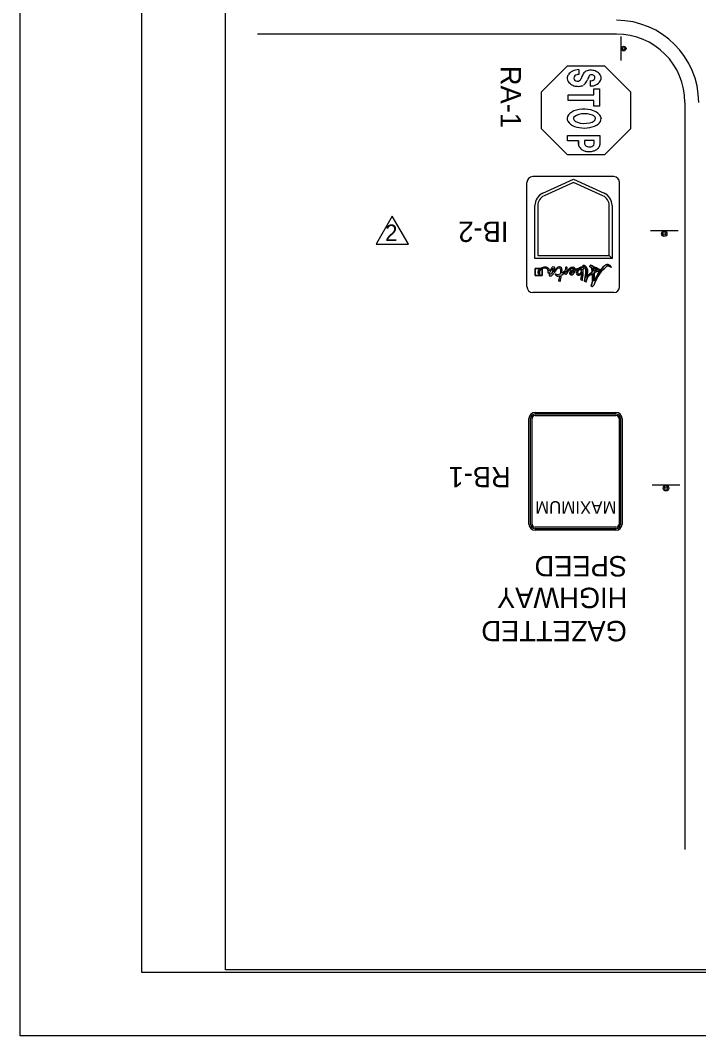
# Model space of a CAD drawing. Extents: x 1482 to 1692, y 225 to 494.
# Drawn here: x 1482.4 to 1542.3, y 224.6 to 314.2 of the extents above; entities that cross this region are included whole.
import ezdxf

# ---------------------------------------------------------------- set-up
doc = ezdxf.new("R2010")
doc.units = 0
for name, color, linetype in [('Level 17', 7, 'Continuous'), ('Level 2', 7, 'Continuous'), ('Level 53', 7, 'Continuous'), ('Level 60', 7, 'Continuous')]:
    doc.layers.add(name, color=color, linetype=linetype)

msp = doc.modelspace()

# ---------------------------------------------------------------- linework, layer by layer
at = {"layer": 'Level 17'}
for p, q in [((1535.424, 312.793), (1535.424, 310.66)), ((1531.14, 309.729), (1531.142, 309.732)), ((1531.708, 309.872), (1531.708, 309.422)), ((1532.74, 308.415), (1532.74, 308.907)), ((1533.04, 307.653), (1533.04, 308.181)), ((1533.04, 308.181), (1533.543, 308.181)), ((1533.543, 308.181), (1533.543, 306.651)), ((1530.78, 307.155), (1530.78, 307.653)), ((1530.78, 307.653), (1533.04, 307.653)), ((1533.028, 307.155), (1530.78, 307.155)), ((1533.028, 306.651), (1533.028, 307.155)), ((1533.543, 306.651), (1533.028, 306.651)), ((1533.182, 305.594), (1533.186, 305.574)), ((1533.67, 305.574), (1533.672, 305.559)), ((1530.696, 303.57), (1530.696, 304.047)), ((1530.696, 304.047), (1533.57, 304.047)), ((1533.57, 304.047), (1533.57, 303.243)), ((1531.676, 303.57), (1530.696, 303.57)), ((1531.676, 303.57), (1531.676, 303.27)), ((1531.683, 303.284), (1531.676, 303.57)), ((1533.054, 303.627), (1532.218, 303.627)), ((1532.218, 303.627), (1532.218, 303.321)), ((1533.054, 303.627), (1532.218, 303.627)), ((1532.218, 303.627), (1532.218, 303.321)), ((1533.054, 303.315), (1533.054, 303.627)), ((1533.054, 303.315), (1533.054, 303.627)), ((1540.463, 295.653), (1538.044, 295.653)), ((1526.756, 289.984), (1526.756, 289.984)), ((1526.756, 289.984), (1526.756, 289.984)), ((1526.756, 289.984), (1526.756, 289.984)), ((1526.756, 289.984), (1526.756, 289.984)), ((1527.854, 279.623), (1534.983, 279.623)), ((1527.304, 269.777), (1527.304, 279.072)), ((1527.441, 269.777), (1527.441, 279.072)), ((1527.578, 269.777), (1527.578, 279.072)), ((1527.854, 279.485), (1534.983, 279.485)), ((1527.854, 279.349), (1534.983, 279.349)), ((1535.26, 279.072), (1535.26, 269.777)), ((1535.396, 279.072), (1535.396, 269.777)), ((1535.534, 279.072), (1535.534, 269.777)), ((1540.616, 273.203), (1538.197, 273.203)), ((1534.983, 269.501), (1527.854, 269.501)), ((1534.983, 269.365), (1527.854, 269.365)), ((1534.983, 269.228), (1527.854, 269.228)), ((1534.983, 269.225), (1534.983, 269.228)), ((1535.11, 269.282), (1535.11, 269.282)), ((1535.235, 269.334), (1535.235, 269.337))]:
    msp.add_line(p, q, dxfattribs=at)
msp.add_lwpolyline([(1530.716, 302.358), (1528.422, 304.652), (1528.422, 307.918), (1530.716, 310.212), (1533.982, 310.212), (1536.274, 307.918), (1536.274, 304.652), (1533.982, 302.358)], close=True, dxfattribs=at)
for centre, radius in [((1535.662, 311.722), 0.213), ((1535.662, 311.722), 0.107), ((1539.249, 295.382), 0.242), ((1539.249, 295.382), 0.121), ((1539.402, 272.932), 0.242), ((1539.402, 272.932), 0.121)]:
    msp.add_circle(centre, radius, dxfattribs=at)
for centre, radius, start, end in [((1531.173, 309.121), 0.489, 142.05359, 202.73967), ((1531.649, 308.788), 1.07, 118.41538, 143.65531), ((1531.775, 308.37), 1.502, 92.38409, 114.95188), ((1531.603, 309.11), 0.335, 140.6966, 181.45727), ((1531.577, 309.135), 0.31, 185.4374, 224.06255), ((1531.572, 309.064), 0.344, 96.87276, 132.74491), ((1531.701, 308.742), 0.685, 89.01715, 103.51721), ((1531.575, 309.184), 0.348, 304.20826, 344.15525), ((1537.06, 307.1), 5.521, 154.46241, 158.83121), ((1532.708, 309.052), 0.762, 110.4481, 145.11069), ((1532.74, 308.738), 1.071, 84.81715, 105.91834), ((1534.051, 308.414), 1.68, 147.98164, 160.97904), ((1532.833, 309.177), 0.242, 74.13099, 148.14758), ((1532.773, 308.587), 1.219, 67.73321, 87.13918), ((1532.871, 309.146), 0.264, 23.8064, 82.24074), ((1532.849, 309.167), 0.277, 317.30173, 19.01194), ((1532.879, 308.921), 0.87, 33.3662, 65.67344), ((1533.152, 309.121), 0.532, 316.13686, 31.39871), ((1531.438, 309.236), 0.782, 203.14132, 234.99056), ((1531.761, 309.717), 1.361, 235.50918, 253.2894), ((1531.574, 309.27), 0.413, 236.25303, 268.73226), ((1531.64, 310.123), 1.731, 261.24702, 273.9864), ((1531.612, 309.174), 0.319, 262.57609, 300.47756), ((1531.637, 309.613), 1.223, 275.90969, 291.9865), ((1533.523, 306.999), 2.053, 129.47897, 133.42605), ((1531.374, 309.4), 1.175, 316.24648, 337.92633), ((1532.801, 309.296), 0.405, 260.44122, 309.32441), ((1532.719, 309.661), 1.243, 270.69518, 287.14515), ((1532.86, 309.343), 0.898, 284.56402, 319.00631), ((1531.846, 303.254), 0.166, 169.79086, 203.54187), ((1532.368, 303.396), 0.706, 196.60197, 209.80906), ((1532.185, 303.253), 0.478, 205.38384, 232.61875), ((1532.407, 303.454), 0.774, 228.29225, 248.60313), ((1532.407, 303.454), 0.774, 228.29225, 248.60313), ((1532.536, 303.387), 0.325, 191.91914, 235.7868), ((1532.536, 303.387), 0.325, 191.91914, 235.7868), ((1532.584, 303.467), 0.418, 236.50855, 267.0313), ((1532.584, 303.467), 0.418, 236.50855, 267.0313), ((1532.641, 303.511), 0.468, 260.34165, 285.23421), ((1532.641, 303.511), 0.468, 260.34165, 285.23421), ((1532.698, 303.495), 0.44, 278.60306, 304.21696), ((1532.698, 303.495), 0.44, 278.60306, 304.21696), ((1532.782, 303.363), 0.283, 305.11978, 349.31166), ((1532.782, 303.363), 0.283, 305.11978, 349.31166), ((1532.888, 303.435), 0.732, 299.22414, 318.53082), ((1532.888, 303.435), 0.732, 299.22414, 318.53082), ((1533.097, 303.285), 0.477, 314.85284, 355.0441), ((1532.711, 304.209), 1.588, 248.31533, 258.66985), ((1532.616, 303.847), 1.215, 259.75207, 272.79164), ((1532.616, 303.847), 1.215, 259.75207, 272.79164), ((1532.587, 304.143), 1.512, 273.39027, 285.65974), ((1532.816, 303.445), 0.778, 283.06738, 303.76202), ((1527.854, 279.072), 0.55, 90, 180), ((1534.983, 279.072), 0.55, 0, 90), ((1527.854, 279.072), 0.413, 90, 180), ((1527.854, 279.072), 0.276, 90, 180), ((1534.983, 279.072), 0.413, 0, 90), ((1534.983, 279.072), 0.276, 0, 90), ((1527.854, 269.776), 0.55, 180, 270), ((1527.854, 269.776), 0.413, 180, 270), ((1527.854, 269.776), 0.276, 180, 270), ((1534.983, 269.776), 0.55, 270, 0), ((1534.983, 269.776), 0.413, 270, 0), ((1534.983, 269.776), 0.276, 270, 0)]:
    msp.add_arc(centre, radius, start, end, dxfattribs=at)
for centre, major_axis, ratio, start_param, end_param in [((1532.175, 305.547), (-1.497, 0.01), 0.558644, 4.129576, 6.939747), ((1532.175, 305.547), (-1.497, 0.01), 0.558644, 0.656861, 3.168126), ((1532.209, 305.547), (-0.977, -0.005), 0.432619, 3.890436, 7.165085), ((1532.209, 305.547), (-0.977, -0.005), 0.432619, 0.881967, 3.190734), ((1532.209, 305.547), (-0.977, -0.005), 0.432619, 3.239639, 3.888884), ((1532.175, 305.547), (-1.497, 0.01), 0.558644, 3.185857, 4.129398)]:
    msp.add_ellipse(centre, major_axis=major_axis, ratio=ratio, start_param=start_param, end_param=end_param, dxfattribs=at)
at = {"layer": 'Level 2'}
for p, q in [((1535.032, 313.009), (1503.354, 313.009)), ((1541.08, 306.96), (1541.08, 241.05)), ((1534.789, 300.427), (1527.647, 300.427)), ((1528.53, 298.962), (1531.239, 300.194)), ((1531.239, 300.194), (1533.948, 298.962)), ((1527.129, 290.722), (1527.129, 299.909)), ((1531.239, 299.913), (1528.636, 298.729)), ((1533.842, 298.729), (1531.239, 299.913)), ((1535.307, 290.722), (1535.307, 299.909)), ((1527.831, 293.208), (1527.831, 297.876)), ((1528.087, 297.876), (1528.087, 293.464)), ((1534.391, 293.464), (1534.391, 297.876)), ((1534.646, 297.876), (1534.646, 293.208)), ((1534.646, 293.208), (1527.831, 293.208)), ((1528.087, 293.464), (1534.391, 293.464)), ((1534.646, 293.208), (1534.391, 293.464)), ((1534.391, 293.464), (1534.646, 293.208)), ((1534.789, 290.204), (1527.647, 290.204)), ((1534.789, 290.204), (1527.647, 290.204))]:
    msp.add_line(p, q, dxfattribs=at)
for centre, radius, start, end in [((1535.032, 306.96), 7.258, 0, 90), ((1535.032, 306.96), 6.048, 0, 90), ((1527.647, 299.909), 0.518, 90, 180), ((1534.789, 299.909), 0.518, 360, 90), ((1529.024, 297.876), 1.193, 114.45682, 180), ((1529.024, 297.876), 0.937, 114.45682, 180), ((1533.454, 297.876), 0.937, 360, 65.54318), ((1533.454, 297.876), 1.193, 360, 65.54318), ((1527.647, 290.722), 0.518, 180, 270), ((1534.789, 290.722), 0.518, 270, 360)]:
    msp.add_arc(centre, radius, start, end, dxfattribs=at)
at = {"layer": 'Level 53'}
msp.add_line((1528.309, 292.319), (1528.459, 292.319), dxfattribs=at)
msp.add_lwpolyline([(1528.309, 292.319), (1527.868, 292.319), (1527.868, 291.711), (1528.476, 291.711), (1528.476, 292.319), (1528.459, 292.319)], dxfattribs=at)
for points, degree in [([(1528.476, 291.711), (1528.476, 291.711), (1528.476, 292.319), (1528.476, 292.319), (1528.476, 292.319), (1528.459, 292.319), (1528.459, 292.319), (1528.327, 292.241), (1528.238, 292.089), (1528.238, 291.965), (1528.239, 291.858), (1528.295, 291.863), (1528.289, 291.848), (1528.271, 291.805), (1528.136, 291.83), (1528.128, 291.981), (1528.122, 292.11), (1528.189, 292.234), (1528.309, 292.319), (1528.309, 292.319), (1527.868, 292.319), (1527.868, 292.319), (1527.868, 292.319), (1527.868, 291.711), (1527.868, 291.711), (1527.868, 291.711), (1528.476, 291.711), (1528.476, 291.711)], 3), ([(1528.459, 292.319), (1528.327, 292.241), (1528.238, 292.089), (1528.238, 291.965), (1528.239, 291.858), (1528.295, 291.863), (1528.289, 291.848), (1528.271, 291.805), (1528.136, 291.83), (1528.128, 291.981), (1528.122, 292.11), (1528.189, 292.234), (1528.309, 292.319)], 3), ([(1529.12, 292.088), (1529.105, 292.214), (1529.022, 292.43), (1528.685, 292.43), (1528.533, 292.43), (1528.404, 292.387), (1528.309, 292.319)], 3), ([(1528.459, 292.319), (1528.515, 292.353), (1528.579, 292.373), (1528.647, 292.373)], 2), ([(1528.647, 292.373), (1528.896, 292.373), (1528.961, 292.18), (1528.973, 292.083), (1528.981, 292.02), (1528.967, 291.927), (1529.077, 291.94), (1529.155, 291.948), (1529.224, 292.098), (1529.322, 292.225), (1529.406, 292.334), (1529.444, 292.323), (1529.424, 292.23), (1529.4, 292.113), (1529.302, 291.839), (1529.191, 291.819), (1529.139, 291.81), (1529.121, 291.901), (1529.097, 291.844), (1529.073, 291.787), (1529.095, 291.665), (1529.211, 291.665), (1529.291, 291.665), (1529.388, 291.75), (1529.468, 291.848), (1529.537, 291.933), (1529.888, 292.448), (1530.035, 292.337), (1530.103, 292.285), (1530.098, 292.073), (1530.054, 291.823)], 3), ([(1529.488, 292.015), (1529.566, 292.191), (1529.61, 292.417), (1529.493, 292.451), (1529.356, 292.491), (1529.247, 292.263), (1529.12, 292.088)], 3), ([(1530.206, 291.901), (1530.234, 292.137), (1530.224, 292.348), (1530.117, 292.414), (1529.92, 292.538), (1529.642, 292.213), (1529.488, 292.015)], 3), ([(1530.182, 291.737), (1530.311, 291.811), (1530.432, 291.936), (1530.52, 292.099)], 2), ([(1530.632, 291.979), (1530.646, 292.125), (1530.741, 292.445), (1530.579, 292.429), (1530.515, 292.422), (1530.543, 292.412), (1530.539, 292.357), (1530.525, 292.164), (1530.365, 292.001), (1530.206, 291.901)], 3), ([(1530.52, 292.099), (1530.505, 292.024), (1530.481, 291.94), (1530.479, 291.884), (1530.478, 291.825), (1530.518, 291.812), (1530.534, 291.807), (1530.568, 291.797), (1530.61, 291.814), (1530.651, 291.872), (1530.747, 292.008), (1530.869, 292.223), (1531.055, 292.313), (1531.187, 292.377), (1531.246, 292.312), (1531.249, 292.212)], 3), ([(1531.391, 292.246), (1531.377, 292.353), (1531.308, 292.435), (1531.145, 292.42), (1530.915, 292.399), (1530.71, 292.116), (1530.632, 291.979)], 3), ([(1531.249, 292.212), (1531.223, 292.204), (1531.199, 292.196), (1531.179, 292.187), (1530.939, 292.08), (1530.856, 291.919), (1530.917, 291.822), (1530.975, 291.728), (1531.141, 291.757), (1531.272, 291.895), (1531.337, 291.963), (1531.387, 292.08), (1531.392, 292.186)], 3), ([(1531.12, 291.907), (1531.04, 291.832), (1531, 291.837), (1530.989, 291.858), (1530.966, 291.901), (1531.061, 292.055), (1531.243, 292.139)], 3), ([(1531.243, 292.139), (1531.227, 292.056), (1531.184, 291.966), (1531.12, 291.907)], 2), ([(1531.632, 292.285), (1531.552, 292.275), (1531.468, 292.262), (1531.391, 292.246)], 2), ([(1531.392, 292.186), (1531.448, 292.198), (1531.512, 292.209), (1531.583, 292.218)], 2), ([(1531.583, 292.218), (1531.47, 292.035), (1531.48, 291.787), (1531.645, 291.745), (1531.837, 291.697), (1531.934, 291.883), (1531.975, 292.038)], 3), ([(1531.934, 292.254), (1531.908, 292.058), (1531.807, 291.787), (1531.68, 291.831), (1531.608, 291.856), (1531.646, 292.084), (1531.739, 292.236)], 3), ([(1532.079, 292.271), (1532.147, 292.293), (1532.175, 292.344), (1532.087, 292.398), (1532.026, 292.436), (1531.893, 292.448), (1531.758, 292.382), (1531.709, 292.358), (1531.667, 292.324), (1531.632, 292.285)], 3), ([(1531.739, 292.236), (1531.801, 292.243), (1531.866, 292.248), (1531.934, 292.254)], 2), ([(1531.788, 292.302), (1531.822, 292.339), (1531.859, 292.365), (1531.9, 292.371)], 2), ([(1531.94, 292.314), (1531.906, 292.312), (1531.852, 292.309), (1531.788, 292.302)], 2), ([(1531.975, 292.038), (1531.963, 291.883), (1531.938, 291.694), (1531.903, 291.519), (1531.888, 291.446), (1531.838, 291.319), (1531.997, 291.294), (1532.048, 291.287), (1532.04, 291.31), (1532.036, 291.378), (1532.03, 291.47), (1532.132, 292.026), (1532.079, 292.271)], 3), ([(1531.9, 292.371), (1531.922, 292.374), (1531.94, 292.374), (1531.955, 292.371)], 2), ([(1531.955, 292.371), (1531.946, 292.364), (1531.941, 292.353), (1531.941, 292.34), (1531.941, 292.332), (1531.94, 292.323), (1531.94, 292.314)], 3), ([(1532.121, 292.54), (1532.187, 292.53), (1532.272, 292.441), (1532.298, 292.295), (1532.345, 292.032), (1532.317, 291.772), (1532.24, 291.384), (1532.225, 291.311), (1532.175, 291.184), (1532.334, 291.159), (1532.385, 291.152), (1532.359, 291.177), (1532.373, 291.244), (1532.434, 291.532), (1532.67, 291.74), (1532.907, 291.879), (1532.932, 291.549), (1532.922, 291.182), (1532.859, 290.957), (1532.807, 290.768), (1532.745, 290.802), (1532.822, 290.763), (1532.903, 290.721), (1532.991, 290.776), (1533.062, 290.917), (1533.133, 291.059), (1533.459, 291.826), (1533.98, 292.345), (1534.247, 292.61), (1534.488, 292.473), (1534.536, 292.432), (1534.575, 292.399), (1534.59, 292.45), (1534.541, 292.503), (1534.325, 292.735), (1534.01, 292.602), (1533.896, 292.487), (1533.579, 292.17), (1533.21, 291.488), (1533.061, 291.199), (1533.075, 291.362), (1533.079, 291.635), (1533.049, 291.955), (1533.21, 292.034), (1533.355, 292.08), (1533.423, 292.098), (1533.497, 292.118), (1533.543, 292.148), (1533.544, 292.182), (1533.546, 292.219), (1533.496, 292.251), (1533.424, 292.285), (1533.297, 292.346), (1532.923, 292.522), (1532.83, 292.576), (1532.752, 292.622), (1532.713, 292.586), (1532.69, 292.537), (1532.659, 292.472), (1532.743, 292.435), (1532.824, 292.411), (1532.855, 292.302), (1532.88, 292.156), (1532.897, 291.996), (1532.707, 291.879), (1532.519, 291.723), (1532.412, 291.528), (1532.439, 291.691), (1532.508, 292.244), (1532.334, 292.478), (1532.295, 292.53), (1532.21, 292.586), (1532.127, 292.578), (1532.088, 292.574), (1532.068, 292.548), (1532.072, 292.54), (1532.076, 292.532), (1532.099, 292.544), (1532.121, 292.54)], 3), ([(1532.412, 291.528), (1532.439, 291.691), (1532.508, 292.244), (1532.334, 292.478), (1532.295, 292.53), (1532.21, 292.586), (1532.127, 292.578), (1532.088, 292.574), (1532.068, 292.548), (1532.072, 292.54), (1532.076, 292.532), (1532.099, 292.544), (1532.121, 292.54)], 3), ([(1532.121, 292.54), (1532.187, 292.53), (1532.272, 292.441), (1532.298, 292.295), (1532.345, 292.032), (1532.317, 291.772), (1532.24, 291.384), (1532.225, 291.311), (1532.175, 291.184), (1532.334, 291.159), (1532.385, 291.152), (1532.359, 291.177), (1532.373, 291.244), (1532.434, 291.532), (1532.67, 291.74), (1532.907, 291.879)], 3), ([(1533.049, 291.955), (1533.21, 292.034), (1533.355, 292.08), (1533.423, 292.098), (1533.497, 292.118), (1533.543, 292.148), (1533.544, 292.182), (1533.546, 292.219), (1533.496, 292.251), (1533.424, 292.285), (1533.297, 292.346), (1532.923, 292.522), (1532.83, 292.576), (1532.752, 292.622), (1532.713, 292.586), (1532.69, 292.537), (1532.659, 292.472), (1532.743, 292.435), (1532.824, 292.411)], 3), ([(1532.907, 291.879), (1532.932, 291.549), (1532.922, 291.182), (1532.859, 290.957), (1532.807, 290.768), (1532.745, 290.802), (1532.822, 290.763), (1532.903, 290.721), (1532.991, 290.776), (1533.062, 290.917), (1533.133, 291.059), (1533.459, 291.826), (1533.98, 292.345), (1534.247, 292.61), (1534.488, 292.473), (1534.536, 292.432), (1534.575, 292.399), (1534.59, 292.45), (1534.541, 292.503), (1534.325, 292.735), (1534.01, 292.602), (1533.896, 292.487), (1533.579, 292.17), (1533.21, 291.488), (1533.061, 291.199)], 3), ([(1532.824, 292.411), (1532.855, 292.302), (1532.88, 292.156), (1532.897, 291.996)], 2), ([(1533.036, 292.075), (1533.021, 292.204), (1533.005, 292.297), (1532.986, 292.366)], 2), ([(1532.986, 292.366), (1533.069, 292.336), (1533.187, 292.288), (1533.341, 292.21)], 2), ([(1533.341, 292.21), (1533.256, 292.179), (1533.149, 292.134), (1533.036, 292.075), (1533.021, 292.204), (1533.005, 292.297), (1532.986, 292.366), (1533.069, 292.336), (1533.187, 292.288), (1533.341, 292.21)], 3), ([(1533.341, 292.21), (1533.256, 292.179), (1533.149, 292.134), (1533.036, 292.075)], 2), ([(1530.054, 291.823), (1529.88, 291.756), (1529.735, 291.778), (1529.653, 291.818), (1529.613, 291.837), (1529.607, 291.834), (1529.624, 291.79), (1529.65, 291.724), (1529.79, 291.622), (1530.009, 291.669), (1530.014, 291.67), (1530.02, 291.671), (1530.025, 291.673)], 3), ([(1530.025, 291.673), (1530.007, 291.591), (1529.987, 291.509), (1529.964, 291.429), (1529.944, 291.356), (1529.883, 291.229), (1530.041, 291.204), (1530.091, 291.196), (1530.069, 291.221), (1530.086, 291.288), (1530.116, 291.413), (1530.155, 291.575), (1530.182, 291.737)], 3), ([(1532.897, 291.996), (1532.707, 291.879), (1532.519, 291.723), (1532.412, 291.528)], 2), ([(1533.061, 291.199), (1533.075, 291.362), (1533.079, 291.635), (1533.049, 291.955)], 2)]:
    msp.add_open_spline(points, degree=degree, dxfattribs=at)
at = {"layer": 'Level 60'}
for points in [[(1482.41, 493.623), (1692.41, 493.623), (1692.41, 224.631), (1482.41, 224.631)], [(1493.127, 487.958), (1687.519, 487.958), (1687.519, 230.208), (1493.127, 230.208)], [(1500.536, 487.818), (1687.41, 487.818), (1687.41, 230.436), (1500.536, 230.436)]]:
    msp.add_lwpolyline(points, close=True, dxfattribs=at)
for points in [[(1515.248, 296.95), (1513.855, 294.525)], [(1516.642, 294.525), (1515.248, 296.95)], [(1513.855, 294.525), (1513.829, 294.48), (1516.668, 294.48), (1516.642, 294.525)]]:
    msp.add_lwpolyline(points, dxfattribs=at)

# ---------------------------------------------------------------- texts
at = {"layer": 'Level 17'}
for s, height, rotation, p in [('RA-1', 1.8, 269.99999, (1524.8, 310.202)), ('IB-2', 1.8, 179.99999, (1525.495, 296.463)), ('RB-1', 1.8, 180, (1525.694, 274.819)), ('MAXIMUM', 1.1106, 180, (1535.033, 271.79)), ('SPEED', 1.8, 180, (1535.964, 266.95)), ('HIGHWAY', 1.8, 180, (1535.99, 264.155)), ('GAZETTED', 1.8, 180, (1535.947, 261.229))]:
    msp.add_text(s, height=height, rotation=rotation, dxfattribs=at).set_placement(p)
at = {"layer": 'Level 60'}
msp.add_text('2', height=1.448, rotation=360, dxfattribs=at).set_placement((1514.621, 294.749))

doc.saveas('drawing.dxf')
